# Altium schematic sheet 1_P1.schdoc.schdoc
size 309 x 223 mm; Symbol: Sheet-Symbol_A4; Device: Sheet-Symbol_A4; Company: EasyEDA.com; Drawed: EasyEDA Pro; Reviewed: EasyEDA Pro; Version: V0.1; Page Size: A4; @Project Name: 2023_11_18_PowerTrack; @Page Count: 1; @Update Date: 2024-03-03; @Create Date: 2024-03-02; @Schematic Name: Power Module; Part Number: JLCPCB-002; @Page No: 1; @Page Name: P1
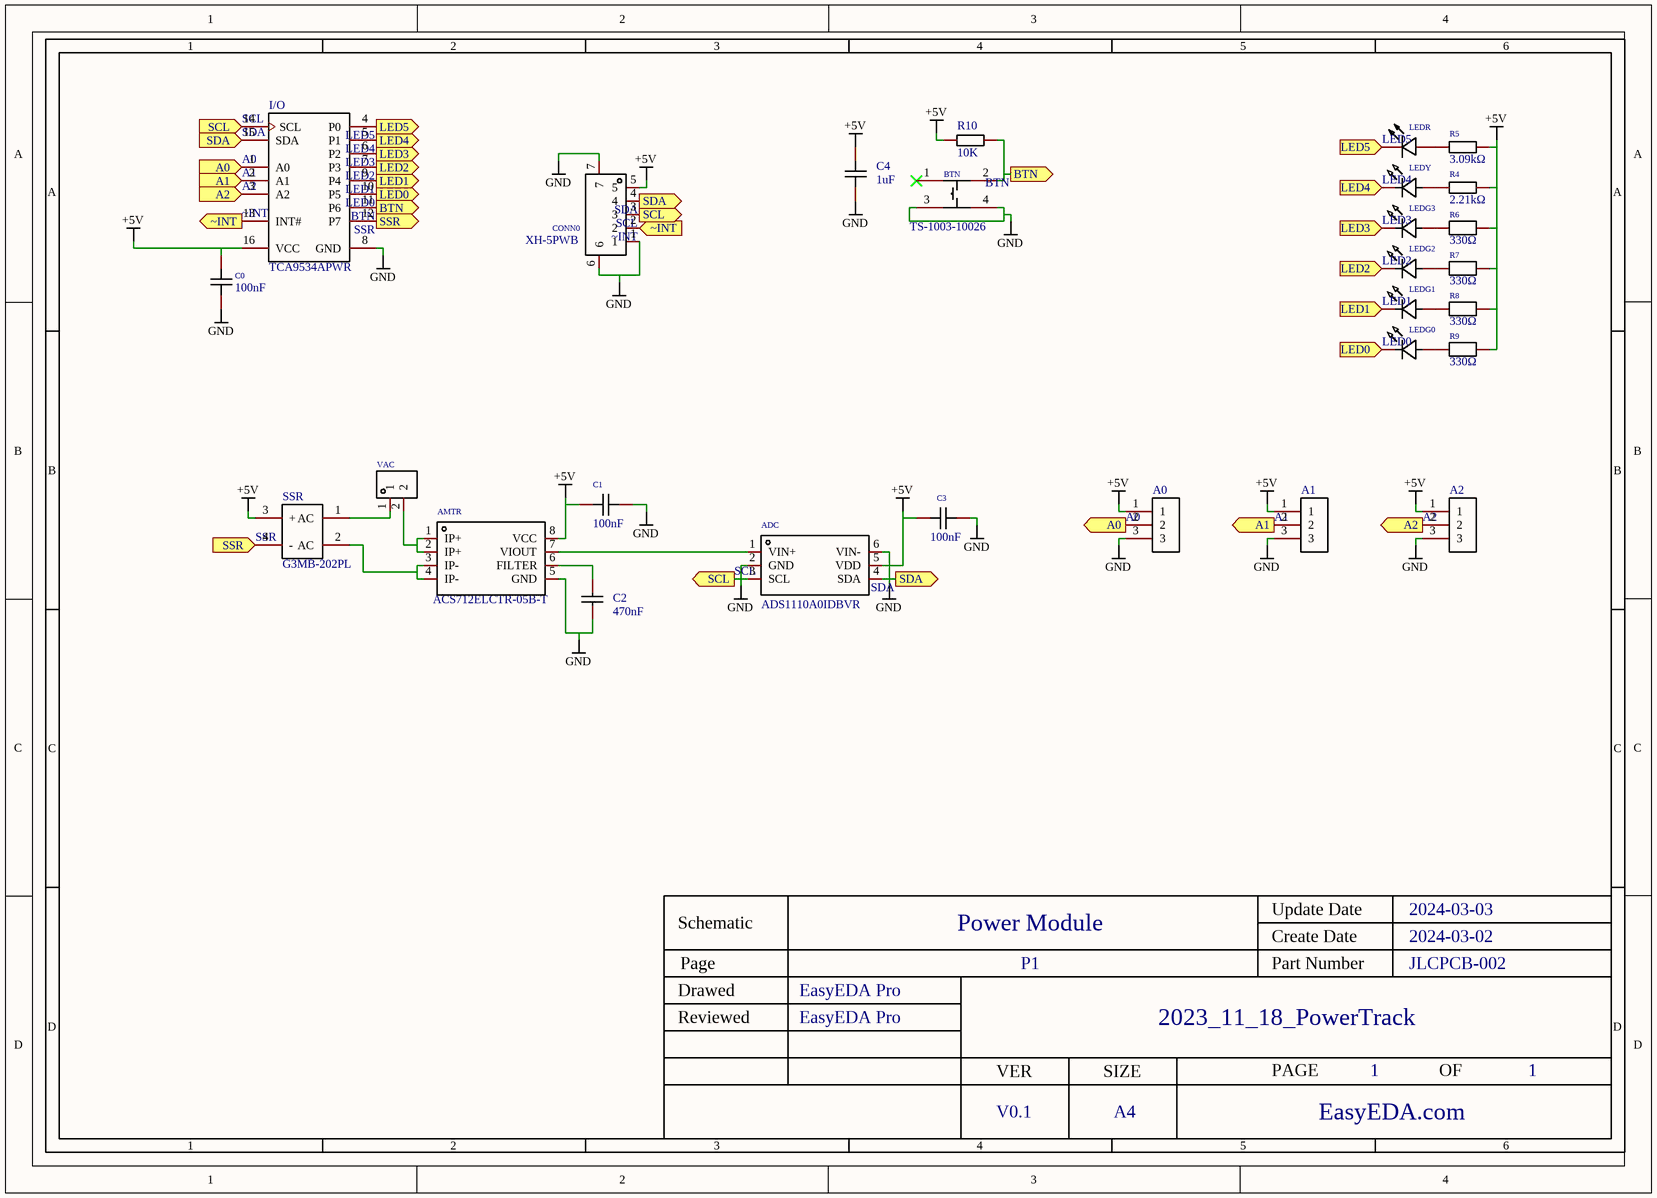
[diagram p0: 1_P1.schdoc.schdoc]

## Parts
A0  Solder Switch  [Solder Switch]  (value not drawn)
A1  Solder Switch  [Solder Switch]  (value not drawn)
A2  Solder Switch  [Solder Switch]  (value not drawn)
ADC  ADS1110A0IDBVR  [SOT-23-6_L2.9-W1.6-P0.95-LS2.8-BR]
AMTR  ACS712ELCTR-05B-T  [SOIC-8_L5.0-W4.0-P1.27-LS6.0-BL]
BTN  TS-1003-10026  [SW-TH_4P-L12.0-W12.0-P5.00-LS12.5]
C0  100nF  [C0805]
C1  100nF  [C0805]
C2  470nF  [C0805]
C3  100nF  [C0805]
C4  1uF  [C0805]
CONN0  XH-5PWB  [CONN-SMD_5P-P2.50_DEALON_XH-5PWB]
I/O  TCA9534APWR  [TSSOP-16_L5.0-W4.4-P0.65-LS6.4-BL]
LEDG0  Green  [LED-TH_L5.0-W2.7-FD]  (value not drawn)
LEDG1  Green  [LED-TH_L5.0-W2.7-FD]  (value not drawn)
LEDG2  Green  [LED-TH_L5.0-W2.7-FD]  (value not drawn)
LEDG3  Green  [LED-TH_L5.0-W2.7-FD]  (value not drawn)
LEDR  Red  [LED-TH_L5.0-W2.7-FD]  (value not drawn)
LEDY  TZ-L2-25FYBY2YCJ150-001  [LED-TH_L5.0-W2.7-FD]  (value not drawn)
R4  2.21kΩ  [R0402]
R5  3.09kΩ  [R0402]
R6  330Ω  [R0402]
R7  330Ω  [R0402]
R8  330Ω  [R0402]
R9  330Ω  [R0402]
R10  10K  [R0805]
SSR  G3MB-202PL  [RELAY-TH_G3MB-202PL]
VAC  XY126V-5.0-2P  [CONN-TH_XY126V-5.0-2P]  (value not drawn)

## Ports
A0 (in), A0 (out), A1 (in), A1 (out), A2 (in), A2 (out), BTN (out), LED0 (in), LED0 (out), LED1 (in), LED1 (out), LED2 (in), LED2 (out), LED3 (in), LED3 (out), LED4 (in), LED4 (out), LED5 (in), LED5 (out), SCL (in), SCL (out), SDA (in), SDA (out), SSR (in), SSR (out), ~INT (in), ~INT (out)

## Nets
+5V: A0.1 A1.1 A2.1 ADC.5(VDD) AMTR.8(VCC) C0.2 C1.2 C3.2 C4.1 CONN0.5 I/O.16(VCC) R4.2 R5.2 R6.2 R7.2 R8.2 R9.2 R10.1 SSR.3(+)
GND: A0.3 A1.3 A2.3 ADC.2(GND) ADC.6(VIN-) AMTR.5(GND) BTN.3 BTN.4 C0.1 C1.1 C2.1 C3.1 C4.2 CONN0.1 CONN0.6 CONN0.7 I/O.8(GND)
A0: A0.2 I/O.1(A0) ; port A0
A1: A1.2 I/O.2(A1) ; port A1
A2: A2.2 I/O.3(A2) ; port A2
BTN: BTN.2 I/O.11(P6) R10.2 ; port BTN
LED0: I/O.10(P5) LEDG0.2(-) ; port LED0
LED1: I/O.9(P4) LEDG1.2(-) ; port LED1
LED2: I/O.7(P3) LEDG2.2(-) ; port LED2
LED3: I/O.6(P2) LEDG3.2(-) ; port LED3
LED4: I/O.5(P1) LEDY.2(-) ; port LED4
LED5: I/O.4(P0) LEDR.2(K) ; port LED5
SCL: ADC.3(SCL) CONN0.3 I/O.14(SCL) ; port SCL
SDA: ADC.4(SDA) CONN0.4 I/O.15(SDA) ; port SDA
SSR: I/O.12(P7) SSR.4(-) ; port SSR
~INT: CONN0.2 I/O.13(INT#) ; port ~INT
NetADC_1: ADC.1(VIN+) AMTR.7(VIOUT)
NetAMTR_1: AMTR.1(IP+) AMTR.2(IP+) VAC.2
NetAMTR_3: AMTR.3(IP-) AMTR.4(IP-) SSR.2(AC)
NetAMTR_6: AMTR.6(FILTER) C2.2
NetLEDG0_1: LEDG0.1(+) R9.1
NetLEDG1_1: LEDG1.1(+) R8.1
NetLEDG2_1: LEDG2.1(+) R7.1
NetLEDG3_1: LEDG3.1(+) R6.1
NetLEDR_1: LEDR.1(A) R5.1
NetLEDY_1: LEDY.1(+) R4.1
NetSSR_1: SSR.1(AC) VAC.1

Not connected (* = marked no-connect by the designer): BTN 1*

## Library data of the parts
A0-A2 = Solder Switch: Add into BOM: yes
ADC = ADS1110A0IDBVR: Manufacturer: TI(德州仪器); Add into BOM: yes; Interface: I2C; number of channels: 1; Supply Voltage: 2.7V~5.5V; sampling frequency: 240Hz; resolution: 16Bit; Description: Interface:I2C differential input:Yes number of channels:1 Supply Voltage:2.7V~5.5V Supply Voltage:2.7V~5.5V sampling frequency:240Hz resolution:16Bit Operating Temperature:-40℃~+125℃ Operating Temperature:-40℃~+125℃
AMTR = ACS712ELCTR-05B-T: Manufacturer: ALLEGRO(美国埃戈罗); Add into BOM: yes; Current Range: 5A; Supply Voltage: 5V; Sensitivity: 185mV/A; Description: Current Range:5A Current Range:5A Supply Voltage:5V Supply Voltage:5V Sensitivity:185mV/A Operating Temperature:-40℃~+85℃ Operating Temperature:-40℃~+85℃
BTN = TS-1003-10026: Manufacturer: XUNPU(讯普); Add into BOM: yes; Contact Current: 50mA; Voltage Rating (DC): 12V; Circuit: SPST; Actuator Style: Round Button; Switch Length: 12mm; Switch Height: 10mm; Description: Contact Current:50mA Voltage Rating (DC):12V Circuit:SPST Mounting Style:Straight Actuator Style:Round Button With Lamp:- Mechanical Life:- Switch Length:12mm Switch Width:12mm Switch Height:10mm
C0 C1 C3 = C2012X7T2E104KT000N: Manufacturer: TDK; Add into BOM: yes; Tolerance: ±10%; Description: Capacitance: Tolerance:±10% Tolerance:±10% Voltage Rated: Temperature Coefficient:
C2 = 0805B181K500NT: Manufacturer: FH(风华); Manufacturer Part: 0805B474K250CT; Add into BOM: yes; Tolerance: ±10%; Description: Capacitance: Tolerance:±10% Tolerance:±10% Voltage Rated: Temperature Coefficient:
C4 = 0805B105K500NT_C215803: Manufacturer: FH(风华); Add into BOM: yes; Tolerance: ±10%; Description: Capacitance:1uF Tolerance:±10% Tolerance:±10% Voltage Rated: Temperature Coefficient:
CONN0 = XH-5PWB: Manufacturer: DEALON(德艺隆); Add into BOM: yes; Pins Structure: 1x5P; Pitch: 2.5mm; Number of PINs Per Row: 5; Reference Series: XH; Current Rating (Max): 3A; Description: Pins Structure:1x5P Pitch:2.5mm Mounting Style:Surface Mount Row Spacing:- Number of Pins:5P Number of Rows:1 Number of PINs Per Row:5 Reference Series:XH Current Rating (Max):3A Operating Temperature Range:-25℃~+85℃ Operating Temperature Range:-25℃~+85℃
I/O = TCA9534APWR: Manufacturer: TI(德州仪器); Add into BOM: yes; Interface: I²C; Number of I/O: 8; Interrupt Output: 有中断输出; Clock Frequency: 400kHz; Supply Voltage: 1.65V~5.5V; Description: Interface:I²C Number of I/O:8 Interrupt Output:有中断输出 Output Type: Clock Frequency:400kHz Supply Voltage:1.65V~5.5V Supply Voltage:1.65V~5.5V Operating Temperature:-40℃~+85℃ Operating Temperature:-40℃~+85℃
LEDG0-LEDG3 = TZ-L2-25FYBYG2YCJ140-001: Manufacturer: TUOZHAN(拓展光电); Add into BOM: yes; Emitted Color: 普绿/Yellow-Green; Dominant Wavelength: 565nm~570nm; Forward Current: 20mA; Power Dissipation: 60mW; Viewing Angle: 140°; Lamp Holder Type: 5mm方形灯头; Description: Emitted Color:普绿/Yellow-Green Diode Configuration:- Lens Color:Green Dominant Wavelength:565nm~570nm Dominant Wavelength:565nm~570nm Peak Wavelength:- Color Temperature:- Color Temperature:- Forward Current:20mA Power Dissipation:60mW Viewing Angle:140° M
LEDR = TJ-L257FGHRMFCSFLC2R-A5: Manufacturer: TOGIALED(统佳); Add into BOM: yes; Emitted Color: 橙红; Lens Color: Red Diffused; Dominant Wavelength: 620nm~630nm; Peak Wavelength: 630nm; Forward Current: 20mA; Power Dissipation: 72mW; Viewing Angle: 110°; Lamp Holder Type: 5mm方形灯头; Description: Emitted Color:橙红 Diode Configuration:- Lens Color:Red Diffused Dominant Wavelength:620nm~630nm Dominant Wavelength:620nm~630nm Peak Wavelength:630nm Color Temperature:- Color Temperature:- Forward Current:20mA Power Dissipation:72mW Viewing Angle:110° Mou
LEDY = TZ-L2-25FYBY2YCJ150-001: Manufacturer: TUOZHAN(拓展光电); Add into BOM: yes; Emitted Color: yellow; Dominant Wavelength: 588nm~593nm; Forward Current: 20mA; Power Dissipation: 60mW; Viewing Angle: 150°; Lamp Holder Type: 5mm方形灯头; Description: Emitted Color:yellow Diode Configuration:- Lens Color:Yellow Dominant Wavelength:588nm~593nm Dominant Wavelength:588nm~593nm Peak Wavelength:- Color Temperature:- Color Temperature:- Forward Current:20mA Power Dissipation:60mW Viewing Angle:150° Mounting
R4 = CR0402FF2211G: Manufacturer: LIZ(丽智电子); Add into BOM: yes; Tolerance: ±1%; Temperature Coefficient: ±200ppm/℃; Description: Type:Thick Film Resistors Resistance: Tolerance:±1% Tolerance:±1% Power(Watts): Overload Voltage (Max): Temperature Coefficient:±200ppm/℃ Temperature Coefficient:±200ppm/℃ Operating Temperature Range:-55℃~+125℃ Operating Temperature Range:-55℃~+125℃
R5 = RTT023091FTH: Manufacturer: RALEC(旺诠); Add into BOM: yes; Tolerance: ±1%; Temperature Coefficient: ±100ppm/℃; Description: Type:Thick Film Resistors Resistance: Tolerance:±1% Tolerance:±1% Power(Watts): Overload Voltage (Max): Temperature Coefficient:±100ppm/℃ Temperature Coefficient:±100ppm/℃ Operating Temperature Range:-55℃~+155℃ Operating Temperature Range:-55℃~+155℃
R6-R9 = 0402WGD3300TCE: Manufacturer: UNI-ROYAL(厚声); Add into BOM: yes; Tolerance: ±0.5%; Temperature Coefficient: ±100ppm/℃; Description: Type:Thick Film Resistors Resistance: Tolerance:±0.5% Tolerance:±0.5% Power(Watts): Overload Voltage (Max): Temperature Coefficient:±100ppm/℃ Temperature Coefficient:±100ppm/℃ Operating Temperature Range:-55℃~+155℃ Operating Temperature Range:-55℃~+155℃
R10 = Res_0805: Symbol: Res; Convert to PCB: yes
SSR = G3MB-202PL: Manufacturer: OMRON(欧姆龙); Add into BOM: yes
VAC = XY126V-5.0-2P: Manufacturer: XINLAIYA(新莱亚); Add into BOM: yes; Structure: 1x2P; Pitch: 5mm; Current Rating (Max): 10A; Voltage Rating (Max): 300V; Wire Gauge - AWG: 14~26; Wire Gauge - mm2: 2.5; Number of PINs Per Row: 2; Description: Structure:1x2P Pitch:5mm Color:Green Mounting Style:Straight Current Rating (Max):10A Voltage Rating (Max):300V Number of Pins:2P Number of Rows:1 Wire Gauge - AWG:14~26 Wire Gauge - AWG:14~26 Wire Gauge - mm2:2.5 Wire Gauge - mm2:2.5 Number of PINs Per R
